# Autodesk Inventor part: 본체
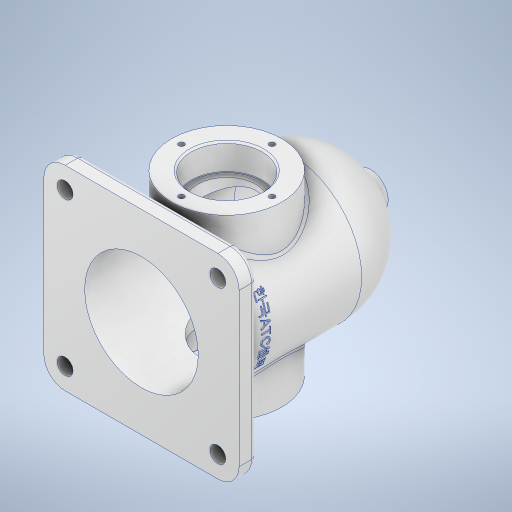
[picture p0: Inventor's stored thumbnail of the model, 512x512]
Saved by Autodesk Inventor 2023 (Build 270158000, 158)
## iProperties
Created: 2025-04
Part Number: 본체
Material: 알루미늄 6061
Document SubType Name: Modeling
Designer: ADMIN_PC
Density: 2.7 g/cm^3
Appearance: 알루미늄 - 평지
Mass: 865.983 g
Surface Area: 800.685 cm^2
Volume: 320.734 cm^3
Author: ADMIN_PC
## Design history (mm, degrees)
sketch "스케치1"
  geometry: C1 r 40 at (0, 0); 1 further point
  constraints: 1 centre point, 1 coincident
  dimensions: "d0" = 80 diameter of C1
extrude "돌출1" new body sketch "스케치1" stored distance "d1" = 84; taper "d2" = 0 deg
sketch "스케치3"
  geometry: L1 (56, 0)-(-56, 0) reference; L2 (0, -58.8)-(0, 58.8) reference; L3 (-40, -42)-(40, -42) reference; L4 (-40, -42)-(-40, 42) reference; L5 (0, -82)-(0, -42); L6 (40, -42)-(0, -42); A1 r 40 centre (0, -42) between (0, -82) and (40, -42); 1 further point
  constraints: 4 end point, 2 point on circle, 1 centre point, 1 collinear, 1 midpoint, 1 perpendicular, 1 point on line
  dimensions: "d4" = 40 radius of A1 (derived)
revolve "회전1" sketch "스케치3" stored, may be unused: angle "d5" = 360 deg
sketch "스케치20"
  geometry: C1 r 10 at (0, 0); 1 further point
  constraints: 1 centre point, 1 coincident
  dimensions: "d55" = 20 diameter of C1
extrude "돌출11" join sketch "스케치20" distance "d56" = 87; taper "d57" = 0 deg
feature "쉘1" dims "d18" = 8
sketch "스케치10"
  geometry: L1 (-58.42, -6)-(71.901, -6); L2 (-32, 42)-(32, 42) reference; L3 (0, -106.8)-(0, 66.8) reference; C1 r 31 at (0, -6); 1 further point
  constraints: 2 end point, 2 point on line, 1 centre point, 1 horizontal
  dimensions: "d20" = 48 distance between parallel lines of L2 L1; "d21" = 62 diameter of C1
extrude "돌출4" join sketch "스케치10" stored distance "d22" = 100; taper "d23" = 0 deg
sketch "스케치12"
  geometry: C1 r 32 at (0, 0); 1 further point
  constraints: 1 centre point, 1 coincident
  dimensions: "d24" = 64 diameter of C1
extrude "돌출5" cut sketch "스케치12" distance "d25" = 84; taper "d26" = 0 deg
sketch "스케치14"
  geometry: L1 (55, -55)-(-55, -55); L2 (-55, -55)-(-55, 55); L3 (-55, 55)-(55, 55); L4 (55, 55)-(55, -55); L5 (55, -55)-(-55, 55); L6 (-55, -55)-(55, 55); 1 further point
  constraints: 12 end point, 2 midpoint, 2 parallel, 1 horizontal, 1 perpendicular
  dimensions: "d27" = 110 distance of L2.end L3.end; "d28" = 110 distance of L1.end L2.end
extrude "돌출6" join sketch "스케치14" distance "d29" = 10; taper "d30" = 0 deg
sketch "스케치15"
  geometry: C1 r 32 at (0, 0); 1 further point
  constraints: 1 centre point, 1 coincident
  dimensions: "d31" = 64 diameter of C1
extrude "돌출7" cut sketch "스케치15" distance "d32" = 10; taper "d33" = 0 deg
sketch "스케치16"
  geometry: L1 (0, -106.8)-(0, 73.8) reference; L2 (73.322, 0)-(-86.169, 0); L3 (-55, 48)-(55, 48) reference; C1 r 16.5 at (0, 0); 1 further point
  constraints: 2 end point, 2 point on line, 1 centre point, 1 horizontal
  dimensions: "d34" = 48 distance between parallel lines of L3 L2; "d35" = 33 diameter of C1
extrude "돌출8" cut sketch "스케치16" extent not by distance; stored distance "d36" = 0; taper "d37" = 0 deg
sketch "스케치17"
  geometry: C1 r 31 at (0, 0) reference; C2 r 20 at (0, 0); 1 further point
  constraints: 1 centre point, 1 coincident
  dimensions: "d38" = 40 diameter of C2
extrude "돌출9" cut sketch "스케치17" distance "d39" = 15; taper "d40" = 0 deg
sketch "스케치18" dims "d41" = 51
  geometry: L1 (0, -106.8)-(0, 73.8) reference; C1 r 31 at (0, 0) reference; 3 further points
  constraints: 1 coincident, 1 point on line, 1 vertical alignment, 2 other
hole "구멍1" sketch "스케치18" at (0, -25.5) diameter "d42" = 3.242; stored, may be unused: countersink angle "d46" = 90 deg, drill point angle "d48" = 118 deg; dims "d43" = 8, "d44" = 4, "d45" = 2, "d47" = 10
sketch "스케치22"
  geometry: 3 further points
  constraints: 2 coincident
hole "구멍2" sketch "스케치22" at (0, 0) diameter "d58" = 4.917; stored, may be unused: countersink angle "d62" = 90 deg, drill point angle "d64" = 0 deg; dims "d59" = 12, "d60" = 4, "d61" = 2, "d63" = 17.1
sketch "스케치23"
  geometry: 1 further point
sketch "스케치24"
  geometry: L1 (-43, -43)-(43, -43); L2 (43, -43)-(43, 43); L3 (43, 43)-(-43, 43); L4 (-43, 43)-(-43, -43); L5 (-43, -43)-(43, 43); L6 (43, -43)-(-43, 43); C1 r 2.458 at (0, 0) reference; C2 r 4.5 at (-43, 43); C3 r 4.5 at (43, 43); C4 r 4.5 at (43, -43); C5 r 4.5 at (-43, -43); 1 further point
  constraints: 12 end point, 4 centre point, 4 coincident, 2 midpoint, 2 parallel, 1 horizontal, 1 perpendicular
  dimensions: "d65" = 86 distance of L3.end L2.end; "d66" = 86 distance of L2.end L1.end; "d67" = 9 diameter of C2; "d68" = 9 diameter of C3; "d69" = 9 diameter of C4; "d70" = 9 diameter of C5
extrude "돌출12" cut sketch "스케치24" distance "d71" = 10; taper "d72" = 0 deg
fillet "모깎기1" dims "d73" = 0.3
fillet "모깎기2" dims "d74" = 12
chamfer "모따기1" distance "d75" = 1; stored, may be unused: second distance "d76" = 2, angle "d77" = 45 deg
fillet "모깎기3" dims "d78" = 3
node "작업 평면2"
sketch "스케치26"
  geometry: L1 (0, -112.8)-(0, 67.8) reference; L2 (43, 42)-(-43, 42) reference; 2 further points
  constraints: 1 point on line, 1 other
  dimensions: "d80" = 30 distance from line of L2 point (0, 12)
feature "엠보싱1" sketch "스케치26" dims "d81" = 0.5, "d82" = 0
feature "̤耀̦耀̨耀̪耀̬耀̮耀̰耀̲耀" dims "d0" = 80, "d1" = 84, "d2" = 0, "d4" = 40 (derived), "d5" = 360 deg, "d18" = 8, "d20" = 48, "d21" = 62, "d22" = 100, "d23" = 0, "d24" = 64, "d25" = 84, "d26" = 0, "d27" = 110, "d28" = 110, "d29" = 10, "d30" = 0, "d31" = 64, "d32" = 10, "d33" = 0, "d34" = 48, "d35" = 33, "d36" = 0, "d37" = 0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
node "솔리드1"
mirror "미러1"
pattern_circular "원형 패턴1" dims angle "d50" = 360 deg
mirror "미러2"
node "작업 평면1"
feature "A9D066F2-1C7D-4E18-AEED-F7BC21143FA4" dims "d42" = 3.242, "d43" = 8, "d44" = 4, "d45" = 2, "d46" = 90 deg, "d47" = 10, "d48" = 118 deg
